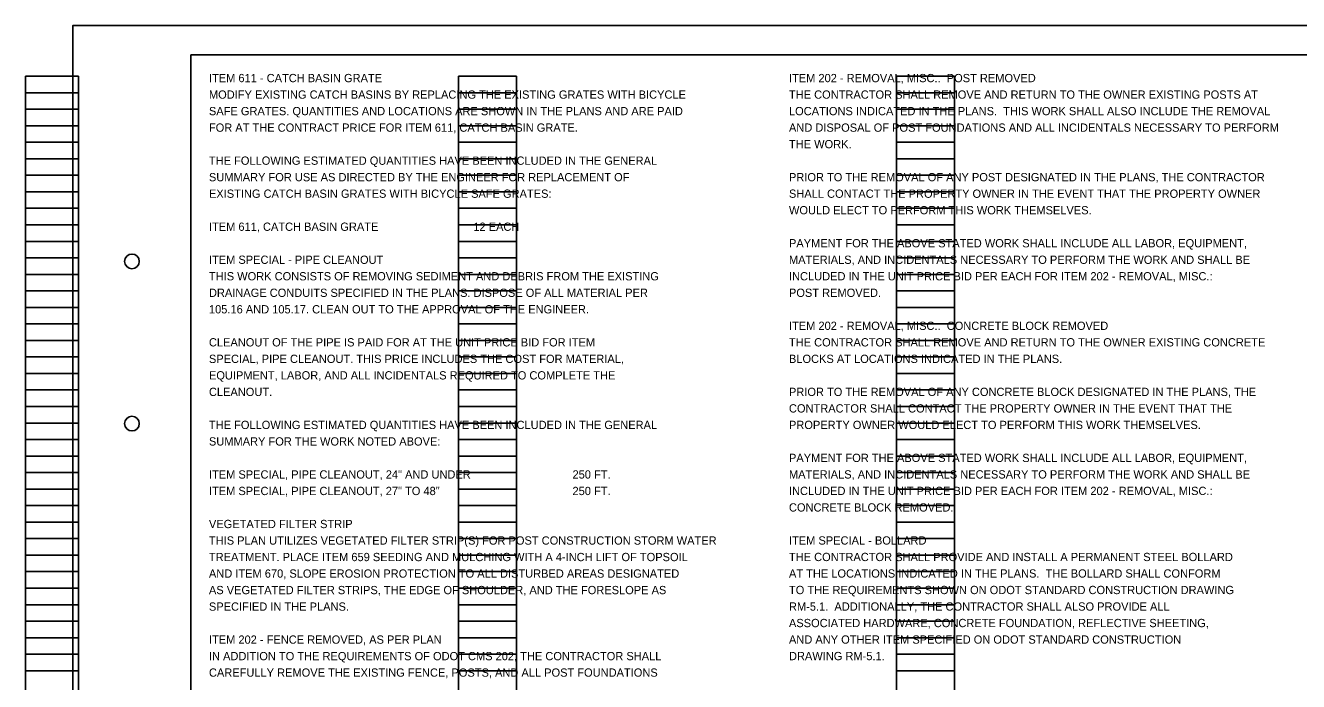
# Model space of a CAD drawing. Extents: x -16 to 195, y -13 to 9.
# Drawn here: x 71.29 to 92.86, y -2.03 to 9.09 of the extents above; entities that cross this region are included whole.
import ezdxf

# ---------------------------------------------------------------- set-up
doc = ezdxf.new("R2010")
doc.units = 0
for name, color, linetype in [('SH_Border', 7, 'Continuous'), ('SH_Cut_Line', 7, 'Continuous'), ('SH_Data', 7, 'Continuous'), ('TX_P_1', 7, 'Continuous')]:
    doc.layers.add(name, color=color, linetype=linetype)

msp = doc.modelspace()

# ---------------------------------------------------------------- linework, layer by layer
at = {"layer": 'SH_Border'}
msp.add_lwpolyline([(74.094, 8.593), (105.594, 8.593), (105.594, -12.407), (74.094, -12.407)], close=True, dxfattribs=at)
for centre in [(73.094, 5.093), (73.094, 2.343)]:
    msp.add_circle(centre, 0.125, dxfattribs=at)
at = {"layer": 'SH_Cut_Line'}
msp.add_lwpolyline([(72.094, -12.907), (106.094, -12.907), (106.094, 9.093), (72.094, 9.093)], close=True, dxfattribs=at)
at = {"layer": 'SH_Data'}
for p, q in [((71.29, -11.927), (71.29, 8.233)), ((71.29, 8.233), (72.19, 8.233)), ((72.19, -11.927), (72.19, 8.233)), ((78.63, -11.927), (78.63, 8.233)), ((78.63, 8.233), (79.61, 8.233)), ((79.61, -11.927), (79.61, 8.233)), ((86.05, -11.927), (86.05, 8.233)), ((86.05, 8.233), (87.03, 8.233)), ((87.03, -11.927), (87.03, 8.233)), ((71.29, 7.953), (72.19, 7.953)), ((78.63, 7.953), (79.61, 7.953)), ((86.05, 7.953), (87.03, 7.953)), ((71.29, 7.673), (72.19, 7.673)), ((78.63, 7.673), (79.61, 7.673)), ((86.05, 7.673), (87.03, 7.673)), ((71.29, 7.393), (72.19, 7.393)), ((78.63, 7.393), (79.61, 7.393)), ((86.05, 7.393), (87.03, 7.393)), ((71.29, 7.113), (72.19, 7.113)), ((78.63, 7.113), (79.61, 7.113)), ((86.05, 7.113), (87.03, 7.113)), ((71.29, 6.833), (72.19, 6.833)), ((78.63, 6.833), (79.61, 6.833)), ((86.05, 6.833), (87.03, 6.833)), ((71.29, 6.553), (72.19, 6.553)), ((78.63, 6.553), (79.61, 6.553)), ((86.05, 6.553), (87.03, 6.553)), ((71.29, 6.273), (72.19, 6.273)), ((78.63, 6.273), (79.61, 6.273)), ((86.05, 6.273), (87.03, 6.273)), ((71.29, 5.993), (72.19, 5.993)), ((78.63, 5.993), (79.61, 5.993)), ((86.05, 5.993), (87.03, 5.993)), ((71.29, 5.713), (72.19, 5.713)), ((78.63, 5.713), (79.61, 5.713)), ((86.05, 5.713), (87.03, 5.713)), ((71.29, 5.433), (72.19, 5.433)), ((78.63, 5.433), (79.61, 5.433)), ((86.05, 5.433), (87.03, 5.433)), ((71.29, 5.153), (72.19, 5.153)), ((78.63, 5.153), (79.61, 5.153)), ((86.05, 5.153), (87.03, 5.153)), ((71.29, 4.873), (72.19, 4.873)), ((78.63, 4.873), (79.61, 4.873)), ((86.05, 4.873), (87.03, 4.873)), ((71.29, 4.593), (72.19, 4.593)), ((78.63, 4.593), (79.61, 4.593)), ((86.05, 4.593), (87.03, 4.593)), ((71.29, 4.313), (72.19, 4.313)), ((78.63, 4.313), (79.61, 4.313)), ((86.05, 4.313), (87.03, 4.313)), ((71.29, 4.033), (72.19, 4.033)), ((78.63, 4.033), (79.61, 4.033)), ((86.05, 4.033), (87.03, 4.033)), ((71.29, 3.753), (72.19, 3.753)), ((78.63, 3.753), (79.61, 3.753)), ((86.05, 3.753), (87.03, 3.753)), ((71.29, 3.473), (72.19, 3.473)), ((78.63, 3.473), (79.61, 3.473)), ((86.05, 3.473), (87.03, 3.473)), ((71.29, 3.193), (72.19, 3.193)), ((78.63, 3.193), (79.61, 3.193)), ((86.05, 3.193), (87.03, 3.193)), ((71.29, 2.913), (72.19, 2.913)), ((78.63, 2.913), (79.61, 2.913)), ((86.05, 2.913), (87.03, 2.913)), ((71.29, 2.633), (72.19, 2.633)), ((78.63, 2.633), (79.61, 2.633)), ((86.05, 2.633), (87.03, 2.633)), ((71.29, 2.353), (72.19, 2.353)), ((78.63, 2.353), (79.61, 2.353)), ((86.05, 2.353), (87.03, 2.353)), ((71.29, 2.073), (72.19, 2.073)), ((78.63, 2.073), (79.61, 2.073)), ((86.05, 2.073), (87.03, 2.073)), ((71.29, 1.793), (72.19, 1.793)), ((78.63, 1.793), (79.61, 1.793)), ((86.05, 1.793), (87.03, 1.793)), ((71.29, 1.513), (72.19, 1.513)), ((78.63, 1.513), (79.61, 1.513)), ((86.05, 1.513), (87.03, 1.513)), ((71.29, 1.233), (72.19, 1.233)), ((78.63, 1.233), (79.61, 1.233)), ((86.05, 1.233), (87.03, 1.233)), ((71.29, 0.953), (72.19, 0.953)), ((78.63, 0.953), (79.61, 0.953)), ((86.05, 0.953), (87.03, 0.953)), ((71.29, 0.673), (72.19, 0.673)), ((78.63, 0.673), (79.61, 0.673)), ((86.05, 0.673), (87.03, 0.673)), ((71.29, 0.393), (72.19, 0.393)), ((78.63, 0.393), (79.61, 0.393)), ((86.05, 0.393), (87.03, 0.393)), ((71.29, 0.113), (72.19, 0.113)), ((78.63, 0.113), (79.61, 0.113)), ((86.05, 0.113), (87.03, 0.113)), ((71.29, -0.167), (72.19, -0.167)), ((78.63, -0.167), (79.61, -0.167)), ((86.05, -0.167), (87.03, -0.167)), ((71.29, -0.447), (72.19, -0.447)), ((78.63, -0.447), (79.61, -0.447)), ((86.05, -0.447), (87.03, -0.447)), ((71.29, -0.727), (72.19, -0.727)), ((78.63, -0.727), (79.61, -0.727)), ((86.05, -0.727), (87.03, -0.727)), ((71.29, -1.007), (72.19, -1.007)), ((78.63, -1.007), (79.61, -1.007)), ((86.05, -1.007), (87.03, -1.007)), ((71.29, -1.287), (72.19, -1.287)), ((78.63, -1.287), (79.61, -1.287)), ((86.05, -1.287), (87.03, -1.287)), ((71.29, -1.567), (72.19, -1.567)), ((78.63, -1.567), (79.61, -1.567)), ((86.05, -1.567), (87.03, -1.567)), ((71.29, -1.847), (72.19, -1.847)), ((78.63, -1.847), (79.61, -1.847)), ((86.05, -1.847), (87.03, -1.847))]:
    msp.add_line(p, q, dxfattribs=at)

# ---------------------------------------------------------------- texts
at = {"layer": 'TX_P_1'}
for s, p in [('ITEM 611 - CATCH BASIN GRATE', (74.399, 8.131)), ('ITEM 202 - REMOVAL, MISC.:  POST REMOVED', (84.227, 8.131)), ('MODIFY EXISTING CATCH BASINS BY REPLACING THE EXISTING GRATES WITH BICYCLE', (74.399, 7.851)), ('THE CONTRACTOR SHALL REMOVE AND RETURN TO THE OWNER EXISTING POSTS AT', (84.227, 7.851)), ('SAFE GRATES. QUANTITIES AND LOCATIONS ARE SHOWN IN THE PLANS AND ARE PAID', (74.399, 7.571)), ('LOCATIONS INDICATED IN THE PLANS.  THIS WORK SHALL ALSO INCLUDE THE REMOVAL', (84.227, 7.571)), ('FOR AT THE CONTRACT PRICE FOR ITEM 611, CATCH BASIN GRATE.', (74.399, 7.291)), ('AND DISPOSAL OF POST FOUNDATIONS AND ALL INCIDENTALS NECESSARY TO PERFORM', (84.227, 7.291)), ('THE WORK.', (84.227, 7.011)), ('THE FOLLOWING ESTIMATED QUANTITIES HAVE BEEN INCLUDED IN THE GENERAL', (74.399, 6.731)), ('SUMMARY FOR USE AS DIRECTED BY THE ENGINEER FOR REPLACEMENT OF', (74.399, 6.451)), ('PRIOR TO THE REMOVAL OF ANY POST DESIGNATED IN THE PLANS, THE CONTRACTOR', (84.227, 6.451)), ('EXISTING CATCH BASIN GRATES WITH BICYCLE SAFE GRATES:', (74.399, 6.171)), ('SHALL CONTACT THE PROPERTY OWNER IN THE EVENT THAT THE PROPERTY OWNER', (84.227, 6.171)), ('WOULD ELECT TO PERFORM THIS WORK THEMSELVES.', (84.227, 5.891)), ('ITEM 611, CATCH BASIN GRATE', (74.399, 5.611)), ('12 EACH', (78.879, 5.611)), ('PAYMENT FOR THE ABOVE STATED WORK SHALL INCLUDE ALL LABOR, EQUIPMENT, ', (84.227, 5.331)), ('ITEM SPECIAL - PIPE CLEANOUT', (74.399, 5.051)), ('MATERIALS, AND INCIDENTALS NECESSARY TO PERFORM THE WORK AND SHALL BE', (84.227, 5.051)), ('THIS WORK CONSISTS OF REMOVING SEDIMENT AND DEBRIS FROM THE EXISTING', (74.399, 4.771)), ('INCLUDED IN THE UNIT PRICE BID PER EACH FOR ITEM 202 - REMOVAL, MISC.:', (84.227, 4.771)), ('DRAINAGE CONDUITS SPECIFIED IN THE PLANS. DISPOSE OF ALL MATERIAL PER', (74.399, 4.491)), ('POST REMOVED.', (84.227, 4.491)), ('105.16 AND 105.17. CLEAN OUT TO THE APPROVAL OF THE ENGINEER.', (74.399, 4.211)), ('ITEM 202 - REMOVAL, MISC.:  CONCRETE BLOCK REMOVED', (84.227, 3.931)), ('CLEANOUT OF THE PIPE IS PAID FOR AT THE UNIT PRICE BID FOR ITEM', (74.399, 3.651)), ('THE CONTRACTOR SHALL REMOVE AND RETURN TO THE OWNER EXISTING CONCRETE', (84.227, 3.651)), ('SPECIAL, PIPE CLEANOUT. THIS PRICE INCLUDES THE COST FOR MATERIAL,', (74.399, 3.371)), ('BLOCKS AT LOCATIONS INDICATED IN THE PLANS.  ', (84.227, 3.371)), ('EQUIPMENT, LABOR, AND ALL INCIDENTALS REQUIRED TO COMPLETE THE', (74.399, 3.091)), ('CLEANOUT.', (74.399, 2.811)), ('PRIOR TO THE REMOVAL OF ANY CONCRETE BLOCK DESIGNATED IN THE PLANS, THE', (84.227, 2.811)), ('CONTRACTOR SHALL CONTACT THE PROPERTY OWNER IN THE EVENT THAT THE', (84.227, 2.531)), ('THE FOLLOWING ESTIMATED QUANTITIES HAVE BEEN INCLUDED IN THE GENERAL', (74.399, 2.251)), ('PROPERTY OWNER WOULD ELECT TO PERFORM THIS WORK THEMSELVES.', (84.227, 2.251)), ('SUMMARY FOR THE WORK NOTED ABOVE:', (74.399, 1.971)), ('PAYMENT FOR THE ABOVE STATED WORK SHALL INCLUDE ALL LABOR, EQUIPMENT, ', (84.227, 1.692)), ('ITEM SPECIAL, PIPE CLEANOUT, 24" AND UNDER', (74.399, 1.411)), ('250 FT.', (80.559, 1.411)), ('MATERIALS, AND INCIDENTALS NECESSARY TO PERFORM THE WORK AND SHALL BE', (84.227, 1.412)), ('ITEM SPECIAL, PIPE CLEANOUT, 27" TO 48"', (74.399, 1.131)), ('250 FT.', (80.559, 1.131)), ('INCLUDED IN THE UNIT PRICE BID PER EACH FOR ITEM 202 - REMOVAL, MISC.: ', (84.227, 1.132)), ('CONCRETE BLOCK REMOVED.', (84.227, 0.852)), ('VEGETATED FILTER STRIP ', (74.399, 0.571)), ('THIS PLAN UTILIZES VEGETATED FILTER STRIP(S) FOR POST CONSTRUCTION STORM WATER', (74.399, 0.291)), ('ITEM SPECIAL - BOLLARD', (84.227, 0.292)), ('TREATMENT. PLACE ITEM 659 SEEDING AND MULCHING WITH A 4-INCH LIFT OF TOPSOIL', (74.399, 0.011)), ('THE CONTRACTOR SHALL PROVIDE AND INSTALL A PERMANENT STEEL BOLLARD', (84.227, 0.012)), ('AND ITEM 670, SLOPE EROSION PROTECTION TO ALL DISTURBED AREAS DESIGNATED', (74.399, -0.269)), ('AT THE LOCATIONS INDICATED IN THE PLANS.  THE BOLLARD SHALL CONFORM', (84.227, -0.268)), ('AS VEGETATED FILTER STRIPS, THE EDGE OF SHOULDER, AND THE FORESLOPE AS', (74.399, -0.549)), ('TO THE REQUIREMENTS SHOWN ON ODOT STANDARD CONSTRUCTION DRAWING', (84.227, -0.548)), ('SPECIFIED IN THE PLANS. ', (74.399, -0.829)), ('RM-5.1.  ADDITIONALLY, THE CONTRACTOR SHALL ALSO PROVIDE ALL', (84.227, -0.828)), ('ASSOCIATED HARDWARE, CONCRETE FOUNDATION, REFLECTIVE SHEETING,', (84.227, -1.108)), ('ITEM 202 - FENCE REMOVED, AS PER PLAN', (74.399, -1.389)), ('AND ANY OTHER ITEM SPECIFIED ON ODOT STANDARD CONSTRUCTION', (84.227, -1.388)), ('IN ADDITION TO THE REQUIREMENTS OF ODOT CMS 202, THE CONTRACTOR SHALL', (74.399, -1.669)), ('DRAWING RM-5.1.', (84.227, -1.668)), ('CAREFULLY REMOVE THE EXISTING FENCE, POSTS, AND ALL POST FOUNDATIONS', (74.399, -1.948))]:
    msp.add_text(s, height=0.14, dxfattribs=at).set_placement(p)

doc.saveas('drawing.dxf')
